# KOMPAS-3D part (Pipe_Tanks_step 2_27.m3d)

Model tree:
1. X Axis
2. Y Axis
3. Z Axis  (labels: T-Bend Dn 50; Pipe Dn 50)
     Òîëùèíà ñòåíêè 1 = 1

Referenced files in C:\Documents and Settings\kashirsky\Мои документы\Camtasia Studio\Pipelines3D\Tanks\: Tanks_step 2.a3d
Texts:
  Pipe Dn 50
  Steel ASTM A295
  Three Point Plane
  Plane at Angle
  Line and Point Plane
  Axis through Two Vertices
  Axis of Feature
  Axis of Conical Surface
  Axis through Edge
  Trim by Surface
  Trim by Sketch
  Feature with No History
  Intersection Axis of Two Planes
  Two Line Plane
  Line and Face Plane
  Bend by line
  Hole in sheet body
  Cut in sheet body
  Point in CM
  Linear Dimension from Line to Point
  Surface Finish Symbol
  Geometric Tolerance Symbol
  Leader #1
  Leader #2
  Leader #3
  Shape Deviations and Datum
  Node point number
  Mark of coordination axis
  Node point designation
  Mark/Reference designation with leader
  Mark/reference designation on line
  Mark/Reference designation without leader
  T-Bend Dn 50
  Plane of section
